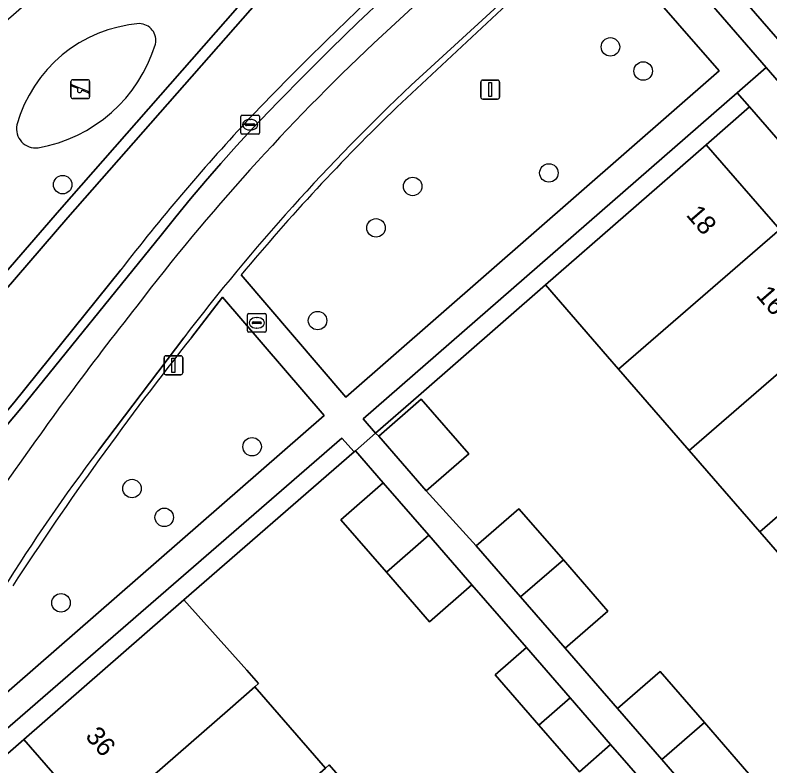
# Model space of a CAD drawing. Extents: x 155887 to 156869, y 383880 to 384678.
# Drawn here: x 156341.97 to 156381.91, y 384143.78 to 384183.51 of the extents above; entities that cross this region are included whole.
import ezdxf

# ---------------------------------------------------------------- set-up
doc = ezdxf.new("R2010")
doc.units = 0
for name, color, linetype in [('IMGEO_Berm_groen', 7, 'Continuous'), ('IMGEO_Boom', 7, 'Continuous'), ('IMGEO_Erf', 7, 'Continuous'), ('IMGEO_Fietspad_gesloten', 7, 'Continuous'), ('IMGEO_Groenvoorziening', 7, 'Continuous'), ('IMGEO_Haag', 7, 'Continuous'), ('IMGEO_Kolk', 7, 'Continuous'), ('IMGEO_Lichtmast', 7, 'Continuous'), ('IMGEO_Muur', 7, 'Continuous'), ('IMGEO_Pand', 7, 'Continuous'), ('IMGEO_Pand_nummerreeks', 7, 'Continuous'), ('IMGEO_Rioolput', 7, 'Continuous'), ('IMGEO_Speelvoorziening', 7, 'Continuous'), ('IMGEO_Terreindeel_zand', 7, 'Continuous'), ('IMGEO_Voetpad_open', 7, 'Continuous')]:
    doc.layers.add(name, color=color, linetype=linetype)

msp = doc.modelspace()

# ---------------------------------------------------------------- linework, layer by layer
at = {"layer": 'IMGEO_Berm_groen'}
for points in [[(156373.848, 384189.824), (156381.718, 384180.744), (156419.983, 384136.598)], [(156391.408, 384171.79), (156376.188, 384189.315)]]:
    msp.add_lwpolyline(points, dxfattribs=at)
at = {"layer": 'IMGEO_Boom'}
for centre in [(156373.473, 384181.83), (156375.205, 384180.551), (156370.214, 384175.159), (156344.487, 384174.54), (156363.008, 384174.443), (156361.068, 384172.252), (156357.973, 384167.345), (156354.51, 384160.669), (156348.156, 384158.455), (156349.859, 384156.93), (156344.399, 384152.407)]:
    msp.add_circle(centre, 0.489, dxfattribs=at)
at = {"layer": 'IMGEO_Erf'}
for points in [[(156414.166, 384140.264), (156380.825, 384178.663), (156378.545, 384176.652), (156382.433, 384172.171), (156386.169, 384167.866), (156389.905, 384163.561), (156393.64, 384159.255), (156397.387, 384154.938), (156401.121, 384150.635), (156404.854, 384146.332), (156408.463, 384142.173), (156408.584, 384142.034), (156411.855, 384138.264), (156412.523, 384138.842)], [(156375.732, 384106.848), (156372.481, 384110.588), (156372.345, 384110.746), (156368.744, 384114.889), (156365.007, 384119.189), (156361.269, 384123.49), (156357.533, 384127.79), (156353.795, 384132.09), (156350.058, 384136.391), (156346.321, 384140.691), (156342.43, 384145.168), (156340.156, 384143.199), (156340.225, 384143.101), (156373.448, 384104.867), (156375.066, 384106.258)]]:
    msp.add_lwpolyline(points, close=True, dxfattribs=at)
for points in [[(156392.587, 384143.245), (156388.853, 384147.547), (156385.117, 384151.853), (156381.381, 384156.158), (156377.643, 384160.464), (156373.907, 384164.768), (156373.321, 384165.444), (156370.036, 384169.229), (156363.309, 384163.36), (156361.044, 384161.384), (156361.213, 384161.232), (156363.46, 384163.186), (156365.971, 384160.295), (156363.723, 384158.342), (156366.372, 384155.424), (156368.632, 384157.387), (156370.982, 384154.681), (156373.332, 384151.974), (156371.072, 384150.011), (156373.852, 384146.811), (156376.109, 384148.771), (156378.456, 384146.068), (156380.803, 384143.366)], [(156376.515, 384141.427), (156373.485, 384144.913), (156371.827, 384143.472), (156369.683, 384145.939), (156367.374, 384148.596), (156369.032, 384150.037), (156366.146, 384153.357), (156363.898, 384151.403), (156361.618, 384154.025), (156359.202, 384156.805), (156361.45, 384158.759), (156359.977, 384160.459), (156359.906, 384160.398), (156350.895, 384152.569), (156354.223, 384148.838), (156354.855, 384148.13), (156354.662, 384147.962), (156358.395, 384143.658), (156358.589, 384143.827), (156362.322, 384139.523)]]:
    msp.add_lwpolyline(points, dxfattribs=at)
at = {"layer": 'IMGEO_Fietspad_gesloten'}
for points in [[(156371.486, 384191.839), (156370.363, 384190.785), (156367.123, 384187.745), (156360.952, 384182.023)], [(156378.947, 384191.657), (156378.887, 384191.6), (156376.295, 384189.305), (156376.188, 384189.315), (156391.408, 384171.79), (156419.571, 384139)], [(156362.931, 384179.804), (156372.335, 384188.435), (156373.848, 384189.824)], [(156346.389, 384160.476), (156350.896, 384166.438)]]:
    msp.add_lwpolyline(points, dxfattribs=at)
for centre, radius, start, end in [((156439.905, 384098.22), 115.137, 133.29344, 142.62619), ((156439.267, 384098.968), 111.183, 133.36015, 142.6389), ((156495.785, 384051.77), 187.764, 141.71246, 145.33862), ((156421.847, 384103.156), 94.761, 142.77863, 148.18386)]:
    msp.add_arc(centre, radius, start, end, dxfattribs=at)
at = {"layer": 'IMGEO_Groenvoorziening'}
for points in [[(156362.607, 384186.101), (156369.178, 384192.157), (156361.631, 384200.724), (156331.521, 384174.522), (156327.46, 384171.061), (156327.723, 384168.516), (156319.647, 384161.786), (156318.439, 384163.205), (156315.287, 384160.478), (156316.645, 384158.911), (156327.376, 384146.523), (156331.408, 384150.854), (156337.184, 384157.409), (156341.904, 384162.995), (156347.557, 384170.029)], [(156359.473, 384163.289), (156379.218, 384180.571), (156372.483, 384188.286), (156362.171, 384178.639)], [(156353.938, 384169.771), (156359.473, 384163.289)], [(156340.8, 384147.039), (156358.331, 384162.33), (156352.943, 384168.577), (156351.303, 384166.451)]]:
    msp.add_lwpolyline(points, dxfattribs=at)
for points in [[(156326.381, 384152.579), (156339.3, 384166.483), (156344.767, 384172.8), (156357.098, 384186.856), (156364.686, 384194.681), (156364.255, 384195.099), (156356.657, 384187.263), (156344.315, 384173.194), (156338.853, 384166.884), (156325.941, 384152.987)], [(156344.767, 384172.8), (156339.3, 384166.483), (156326.381, 384152.579), (156325.941, 384152.987), (156338.853, 384166.884), (156344.315, 384173.194), (156356.657, 384187.263), (156364.255, 384195.099), (156364.686, 384194.681), (156357.098, 384186.856)], [(156363.309, 384163.36), (156370.036, 384169.229), (156378.545, 384176.652), (156380.825, 384178.663), (156380.181, 384179.404), (156360.384, 384162.143), (156361.044, 384161.384)], [(156359.906, 384160.398), (156359.254, 384161.13), (156333.847, 384139.086), (156334.608, 384138.293), (156340.225, 384143.101), (156340.156, 384143.199), (156342.43, 384145.168), (156350.895, 384152.569)]]:
    msp.add_lwpolyline(points, close=True, dxfattribs=at)
for centre, radius, start, end in [((156476.826, 384061.083), 169.338, 132.41568, 136.4105), ((156349.133, 384175.755), 7.329, 94.568, 164.5965), ((156348.53, 384182.176), 0.885, 346.8773, 88.763), ((156341.836, 384184.271), 7.897, 279.8338, 343.0989), ((156439.012, 384099.044), 110.634, 133.99163, 140.26147), ((156439.689, 384098.678), 116.53, 137.20886, 142.24415), ((156343.061, 384177.497), 1.015, 168.3469, 277.0326), ((156484.65, 384060.541), 170.289, 141.5418, 146.99474)]:
    msp.add_arc(centre, radius, start, end, dxfattribs=at)
at = {"layer": 'IMGEO_Haag'}
for points in [[(156326.381, 384152.579), (156339.3, 384166.483), (156344.767, 384172.8), (156357.098, 384186.856), (156364.686, 384194.681), (156364.255, 384195.099), (156356.657, 384187.263), (156344.315, 384173.194), (156338.853, 384166.884), (156325.941, 384152.987)], [(156363.309, 384163.36), (156370.036, 384169.229), (156378.545, 384176.652), (156380.825, 384178.663), (156380.181, 384179.404), (156360.384, 384162.143), (156361.044, 384161.384)], [(156342.43, 384145.168), (156350.895, 384152.569), (156359.906, 384160.398), (156359.254, 384161.13), (156333.847, 384139.086), (156334.608, 384138.293), (156340.225, 384143.101), (156340.156, 384143.199)]]:
    msp.add_lwpolyline(points, close=True, dxfattribs=at)
at = {"layer": 'IMGEO_Kolk'}
for p, q in [((156353.982, 384178.211), (156354.834, 384178.211)), ((156353.907, 384177.285), (156353.907, 384178.137)), ((156354.209, 384177.754), (156354.607, 384177.754)), ((156354.395, 384177.991), (156354.42, 384177.991)), ((156354.908, 384178.137), (156354.908, 384177.285)), ((156354.166, 384177.705), (156354.166, 384177.717)), ((156354.604, 384177.668), (156354.206, 384177.668)), ((156354.418, 384177.431), (156354.393, 384177.431)), ((156354.65, 384177.717), (156354.65, 384177.705)), ((156354.834, 384177.211), (156353.982, 384177.211))]:
    msp.add_line(p, q, dxfattribs=at)
for points in [[(156353.982, 384178.211), (156354.834, 384178.211)], [(156353.907, 384177.285), (156353.907, 384178.137)], [(156354.908, 384178.137), (156354.908, 384177.285)], [(156354.834, 384177.211), (156353.982, 384177.211)]]:
    msp.add_lwpolyline(points, dxfattribs=at)
for centre, radius, start, end in [((156353.984, 384178.135), 0.0765, 91.552, 178.448), ((156353.984, 384178.135), 0.0765, 91.552, 178.448), ((156354.832, 384178.135), 0.0765, 1.552, 88.448), ((156354.832, 384178.135), 0.0765, 1.552, 88.448), ((156354.206, 384177.714), 0.0403, 85.8775, 175.7526), ((156354.611, 384177.716), 0.0386, 1.7309, 96.639), ((156354.203, 384177.704), 0.0366, 178.938, 274.7102), ((156354.607, 384177.711), 0.043, 264.8664, 352.4533), ((156353.984, 384177.287), 0.0765, 181.552, 268.448), ((156353.984, 384177.287), 0.0765, 181.552, 268.448), ((156354.832, 384177.287), 0.0765, 271.552, 358.448), ((156354.832, 384177.287), 0.0765, 271.552, 358.448)]:
    msp.add_arc(centre, radius, start, end, dxfattribs=at)
for centre, major_axis, ratio, start_param, end_param in [((156354.394, 384177.711), (-0.387, 0.002), 0.722429, 4.712389, 7.853982), ((156354.419, 384177.711), (-0.39, 0.002), 0.717154, 1.570796, 4.712389)]:
    msp.add_ellipse(centre, major_axis=major_axis, ratio=ratio, start_param=start_param, end_param=end_param, dxfattribs=at)
at = {"layer": 'IMGEO_Lichtmast'}
for p, q in [((156366.615, 384179.171), (156366.615, 384179.971)), ((156366.615, 384179.971), (156366.615, 384179.171)), ((156366.715, 384180.071), (156367.505, 384180.071)), ((156367.505, 384180.071), (156366.715, 384180.071)), ((156367.605, 384179.971), (156367.605, 384179.171)), ((156367.605, 384179.171), (156367.605, 384179.971)), ((156367.505, 384179.071), (156366.715, 384179.071)), ((156366.715, 384179.071), (156367.505, 384179.071)), ((156349.85, 384164.579), (156349.85, 384165.379)), ((156349.85, 384165.379), (156349.85, 384164.579)), ((156349.95, 384165.479), (156350.74, 384165.479)), ((156350.74, 384165.479), (156349.95, 384165.479)), ((156350.84, 384165.379), (156350.84, 384164.579)), ((156350.84, 384164.579), (156350.84, 384165.379)), ((156350.74, 384164.479), (156349.95, 384164.479)), ((156349.95, 384164.479), (156350.74, 384164.479))]:
    msp.add_line(p, q, dxfattribs=at)
for points in [[(156367.035, 384179.946), (156367.185, 384179.946), (156367.185, 384179.196), (156367.035, 384179.196), (156367.035, 384179.946)], [(156350.27, 384165.354), (156350.42, 384165.354), (156350.42, 384164.604), (156350.27, 384164.604), (156350.27, 384165.354)]]:
    msp.add_lwpolyline(points, dxfattribs=at)
for centre, start, end in [((156366.715, 384179.971), 90, 180), ((156366.715, 384179.971), 90, 180), ((156367.505, 384179.971), 0, 90), ((156367.505, 384179.971), 360, 90), ((156366.715, 384179.171), 180, 270), ((156366.715, 384179.171), 180, 270), ((156367.505, 384179.171), 270, 0), ((156367.505, 384179.171), 270, 0), ((156349.95, 384165.379), 90, 180), ((156349.95, 384165.379), 90, 180), ((156350.74, 384165.379), 0, 90), ((156350.74, 384165.379), 360, 90), ((156349.95, 384164.579), 180, 270), ((156349.95, 384164.579), 180, 270), ((156350.74, 384164.579), 270, 0), ((156350.74, 384164.579), 270, 0)]:
    msp.add_arc(centre, 0.1, start, end, dxfattribs=at)
at = {"layer": 'IMGEO_Muur'}
msp.add_lwpolyline([(156370.036, 384169.229), (156363.309, 384163.36)], dxfattribs=at)
at = {"layer": 'IMGEO_Pand'}
for points in [[(156382.433, 384172.171), (156378.545, 384176.652), (156370.036, 384169.229), (156373.321, 384165.444), (156373.907, 384164.768)], [(156382.433, 384172.171), (156373.907, 384164.768), (156377.643, 384160.464), (156386.169, 384167.866)], [(156377.643, 384160.464), (156381.381, 384156.158), (156389.905, 384163.561), (156386.169, 384167.866)], [(156393.64, 384159.255), (156389.905, 384163.561), (156381.381, 384156.158), (156385.117, 384151.853)], [(156361.213, 384161.232), (156363.723, 384158.342), (156365.971, 384160.295), (156363.46, 384163.186)], [(156361.618, 384154.025), (156363.864, 384155.983), (156361.45, 384158.759), (156359.202, 384156.805)], [(156368.721, 384152.718), (156370.982, 384154.681), (156368.632, 384157.387), (156366.372, 384155.424)], [(156361.618, 384154.025), (156363.898, 384151.403), (156366.146, 384153.357), (156363.864, 384155.983)], [(156368.721, 384152.718), (156371.072, 384150.011), (156373.332, 384151.974), (156370.982, 384154.681)], [(156354.662, 384147.962), (156354.855, 384148.13), (156354.223, 384148.838), (156350.895, 384152.569), (156342.43, 384145.168), (156346.321, 384140.691), (156353.349, 384146.817)], [(156369.683, 384145.939), (156371.339, 384147.383), (156369.032, 384150.037), (156367.374, 384148.596)], [(156378.456, 384146.068), (156376.109, 384148.771), (156373.852, 384146.811), (156376.199, 384144.108)], [(156357.082, 384142.514), (156358.395, 384143.658), (156354.662, 384147.962), (156353.349, 384146.817), (156346.321, 384140.691), (156350.058, 384136.391)], [(156369.683, 384145.939), (156371.827, 384143.472), (156373.485, 384144.913), (156371.339, 384147.383)], [(156378.456, 384146.068), (156376.199, 384144.108), (156378.546, 384141.406), (156380.803, 384143.366)], [(156362.322, 384139.523), (156358.589, 384143.827), (156358.395, 384143.658), (156357.082, 384142.514), (156350.058, 384136.391), (156353.795, 384132.09)]]:
    msp.add_lwpolyline(points, close=True, dxfattribs=at)
at = {"layer": 'IMGEO_Rioolput'}
for p, q in [((156354.258, 384166.802), (156354.258, 384167.654)), ((156354.333, 384167.728), (156355.185, 384167.728)), ((156354.746, 384167.508), (156354.771, 384167.508)), ((156355.259, 384167.654), (156355.259, 384166.802)), ((156354.517, 384167.222), (156354.517, 384167.234)), ((156354.955, 384167.185), (156354.557, 384167.185)), ((156354.56, 384167.271), (156354.958, 384167.271)), ((156355.001, 384167.234), (156355.001, 384167.222)), ((156355.185, 384166.728), (156354.333, 384166.728)), ((156354.769, 384166.948), (156354.744, 384166.948))]:
    msp.add_line(p, q, dxfattribs=at)
for points in [[(156354.258, 384166.802), (156354.258, 384167.654)], [(156354.333, 384167.728), (156355.185, 384167.728)], [(156355.259, 384167.654), (156355.259, 384166.802)], [(156355.185, 384166.728), (156354.333, 384166.728)]]:
    msp.add_lwpolyline(points, dxfattribs=at)
for centre, radius, start, end in [((156354.335, 384167.652), 0.0765, 91.552, 178.448), ((156354.335, 384167.652), 0.0765, 91.552, 178.448), ((156355.183, 384167.652), 0.0765, 1.552, 88.448), ((156355.183, 384167.652), 0.0765, 1.552, 88.448), ((156354.557, 384167.231), 0.0403, 85.8775, 175.7526), ((156354.554, 384167.221), 0.0366, 178.938, 274.7102), ((156354.958, 384167.228), 0.043, 264.8664, 352.4533), ((156354.962, 384167.233), 0.0386, 1.7309, 96.639), ((156354.335, 384166.804), 0.0765, 181.552, 268.448), ((156354.335, 384166.804), 0.0765, 181.552, 268.448), ((156355.183, 384166.804), 0.0765, 271.552, 358.448), ((156355.183, 384166.804), 0.0765, 271.552, 358.448)]:
    msp.add_arc(centre, radius, start, end, dxfattribs=at)
for centre, major_axis, ratio, start_param, end_param in [((156354.745, 384167.228), (-0.387, 0.002), 0.722429, 4.712389, 7.853982), ((156354.77, 384167.228), (-0.39, 0.002), 0.717154, 1.570796, 4.712389)]:
    msp.add_ellipse(centre, major_axis=major_axis, ratio=ratio, start_param=start_param, end_param=end_param, dxfattribs=at)
at = {"layer": 'IMGEO_Speelvoorziening'}
for p, q in [((156344.921, 384179.192), (156344.921, 384179.992)), ((156344.921, 384179.992), (156344.921, 384179.192)), ((156345.304, 384179.62), (156344.965, 384179.757)), ((156344.99, 384179.817), (156345.866, 384179.464)), ((156345.021, 384180.092), (156345.811, 384180.092)), ((156345.811, 384180.092), (156345.021, 384180.092)), ((156345.911, 384179.992), (156345.911, 384179.192)), ((156345.911, 384179.192), (156345.911, 384179.992)), ((156345.842, 384179.404), (156345.502, 384179.541)), ((156345.811, 384179.092), (156345.021, 384179.092)), ((156345.021, 384179.092), (156345.811, 384179.092))]:
    msp.add_line(p, q, dxfattribs=at)
for centre, radius, start, end in [((156345.021, 384179.992), 0.1, 90, 180), ((156345.021, 384179.992), 0.1, 90, 180), ((156344.978, 384179.787), 0.0327, 68.078, 248.078), ((156345.811, 384179.992), 0.1, 0, 90), ((156345.811, 384179.992), 0.1, 360, 90), ((156345.383, 384179.53), 0.12, 130.9928, 5.1632), ((156345.854, 384179.434), 0.0327, 248.078, 68.078), ((156345.021, 384179.192), 0.1, 180, 270), ((156345.021, 384179.192), 0.1, 180, 270), ((156345.811, 384179.192), 0.1, 270, 0), ((156345.811, 384179.192), 0.1, 270, 0)]:
    msp.add_arc(centre, radius, start, end, dxfattribs=at)
at = {"layer": 'IMGEO_Terreindeel_zand'}
for centre, radius, start, end in [((156349.133, 384175.755), 7.329, 94.568, 164.5965), ((156348.53, 384182.176), 0.885, 346.8773, 88.763), ((156341.836, 384184.271), 7.897, 279.8338, 343.0989), ((156343.061, 384177.497), 1.015, 168.3469, 277.0326)]:
    msp.add_arc(centre, radius, start, end, dxfattribs=at)
at = {"layer": 'IMGEO_Voetpad_open'}
for points in [[(156342.272, 384162.695), (156349.691, 384171.874), (156350.467, 384172.836), (156351.254, 384173.788), (156352.053, 384174.731), (156352.863, 384175.664), (156353.684, 384176.587), (156354.516, 384177.5), (156355.889, 384178.926), (156357.278, 384180.336), (156358.681, 384181.732), (156360.099, 384183.112), (156361.532, 384184.477), (156362.98, 384185.827), (156369.476, 384191.797), (156369.178, 384192.157), (156362.607, 384186.101)], [(156380.181, 384179.404), (156381.718, 384180.744), (156373.848, 384189.824), (156372.335, 384188.435), (156362.931, 384179.804)], [(156362.171, 384178.639), (156372.483, 384188.286), (156379.218, 384180.571), (156359.473, 384163.289)], [(156360.952, 384182.023), (156367.123, 384187.745)], [(156361.532, 384184.477), (156360.099, 384183.112), (156358.681, 384181.732), (156357.278, 384180.336), (156355.889, 384178.926), (156354.516, 384177.5), (156353.684, 384176.587), (156352.863, 384175.664), (156352.053, 384174.731), (156351.254, 384173.788), (156350.467, 384172.836), (156349.691, 384171.874), (156342.272, 384162.695), (156337.547, 384157.079), (156336.611, 384155.967), (156335.665, 384154.863), (156334.708, 384153.768), (156333.741, 384152.682), (156332.765, 384151.605), (156331.778, 384150.537), (156327.699, 384146.15), (156326.352, 384144.787)], [(156419.983, 384136.598), (156381.718, 384180.744), (156380.181, 384179.404), (156380.825, 384178.663), (156414.166, 384140.264)], [(156323.467, 384130.447), (156323.647, 384130.219), (156332.386, 384137.74), (156333.088, 384136.971), (156334.608, 384138.293), (156333.847, 384139.086), (156359.254, 384161.13), (156359.906, 384160.398), (156359.977, 384160.459), (156361.044, 384161.384), (156360.384, 384162.143), (156380.181, 384179.404)], [(156347.557, 384170.029), (156341.904, 384162.995), (156337.184, 384157.409), (156331.408, 384150.854), (156327.376, 384146.523), (156327.699, 384146.15), (156331.778, 384150.537), (156332.765, 384151.605), (156333.741, 384152.682), (156334.708, 384153.768), (156335.665, 384154.863), (156336.611, 384155.967), (156337.547, 384157.079), (156342.272, 384162.695)], [(156359.473, 384163.289), (156353.938, 384169.771)], [(156351.303, 384166.451), (156352.943, 384168.577), (156358.331, 384162.33), (156340.8, 384147.039)], [(156350.896, 384166.438), (156346.389, 384160.476)], [(156378.546, 384141.406), (156376.199, 384144.108), (156373.852, 384146.811), (156371.072, 384150.011), (156368.721, 384152.718), (156366.372, 384155.424), (156363.723, 384158.342), (156361.213, 384161.232), (156361.044, 384161.384), (156359.977, 384160.459), (156361.45, 384158.759), (156363.864, 384155.983), (156366.146, 384153.357), (156369.032, 384150.037), (156371.339, 384147.383), (156373.485, 384144.913), (156376.515, 384141.427)]]:
    msp.add_lwpolyline(points, dxfattribs=at)
for centre, radius, start, end in [((156476.826, 384061.083), 169.338, 132.41568, 136.4105), ((156439.905, 384098.22), 115.137, 133.29344, 142.62619), ((156439.267, 384098.968), 111.183, 133.36015, 142.6389), ((156439.012, 384099.044), 110.634, 133.99163, 140.26147), ((156439.689, 384098.678), 116.53, 137.20886, 142.24415), ((156495.785, 384051.77), 187.764, 141.71246, 145.33862), ((156484.65, 384060.541), 170.289, 141.5418, 146.99474), ((156421.847, 384103.156), 94.761, 142.77863, 148.18386)]:
    msp.add_arc(centre, radius, start, end, dxfattribs=at)

# ---------------------------------------------------------------- texts
at = {"layer": 'IMGEO_Pand_nummerreeks'}
for s, rotation, p in [('18', 310.9488, (156377.438, 384172.923)), ('16', 310.9488, (156381.137, 384168.66)), ('36', 310.9949, (156345.641, 384145.316))]:
    msp.add_text(s, height=1, rotation=rotation, dxfattribs=at).set_placement(p)

doc.saveas('drawing.dxf')
